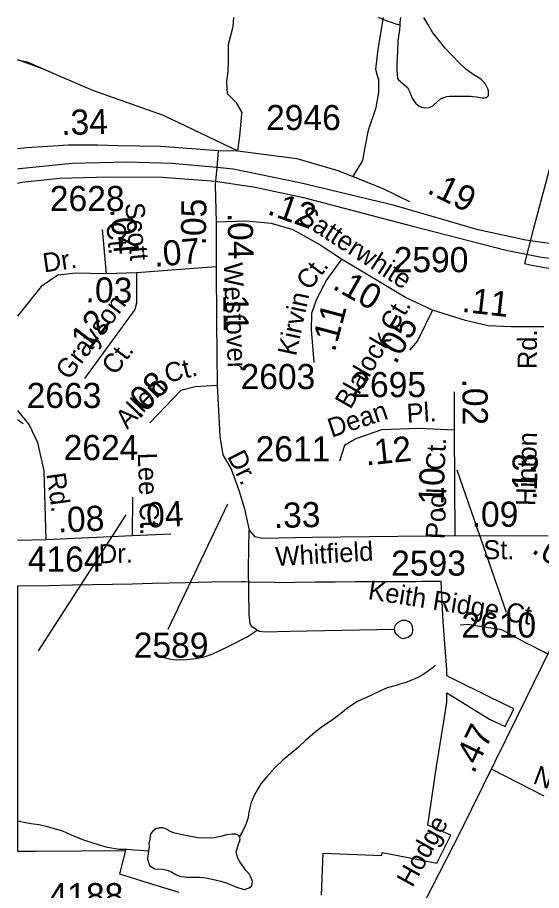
# Model space of a CAD drawing. Extents: x 2169602 to 2449496, y 721995 to 810662.
# Drawn here: x 2379098 to 2381705, y 806315 to 810662 of the extents above; entities that cross this region are included whole.
import ezdxf

# ---------------------------------------------------------------- set-up
doc = ezdxf.new("R2010")
doc.units = 0
doc.layers.add('Default', color=7, linetype='Continuous')

msp = doc.modelspace()

# ---------------------------------------------------------------- linework, layer by layer
at = {"layer": 'Default'}
for p, q in [((2379126, 808638.6), (2379098.1, 808658.4)), ((2381284, 808409.5), (2381529.1, 807700.8)), ((2379670.9, 808080.7), (2379671.6, 808273.1)), ((2380143.7, 808238.9), (2379845.3, 807615.5)), ((2379637.5, 808185.7), (2379200.6, 807509)), ((2379098.1, 807830.9), (2379098.1, 806511.6)), ((2379098.1, 807830.9), (2379098.1, 806511.6)), ((2381454.4, 806921), (2381716.7, 806787.4))]:
    msp.add_line(p, q, dxfattribs=at)
for points in [[(2380143.7, 810371.9), (2380144.2, 810376.4), (2380148.1, 810425.5), (2380148.1, 810527.6), (2380171.5, 810617.4), (2380173.9, 810661.8)], [(2380889.3, 810371.9), (2380880.1, 810401.9), (2380891.9, 810504), (2380919.1, 810661.8)], [(2381000.4, 810623), (2380986.2, 810627.2), (2380954.1, 810638.9), (2380928.2, 810646.9), (2380894.5, 810661.8)], [(2381000.4, 810623), (2380998.3, 810601), (2380990.4, 810545), (2380988.7, 810491.3), (2380984.8, 810433), (2380985.2, 810397.3), (2380989.1, 810359), (2380993.6, 810351), (2381027.3, 810323.2), (2381037.7, 810313.5), (2381049.8, 810289.4), (2381055.8, 810271.4), (2381063.6, 810257.7), (2381067.9, 810249.7), (2381080, 810233.7), (2381096, 810219.5), (2381108.1, 810215.6), (2381127.7, 810211.8), (2381146, 810213.9), (2381163.8, 810221.8), (2381188, 810244.1), (2381202, 810256.2), (2381213.9, 810262.1), (2381233.7, 810268.4), (2381247.7, 810270.4), (2381255.7, 810270.4), (2381279.5, 810270.4), (2381311.9, 810270.4), (2381329.7, 810270.5), (2381353.5, 810270.6), (2381363.8, 810268.6), (2381381.8, 810266.7), (2381409.7, 810260.9), (2381421.6, 810261.1), (2381429.6, 810263.2), (2381437.8, 810269.2), (2381441.5, 810273.1), (2381441.5, 810281.2), (2381441.7, 810297), (2381437.8, 810306.9), (2381425.7, 810329), (2381413.4, 810345.1), (2381403.1, 810354.8), (2381373, 810372.7), (2381351, 810388.6), (2381329.1, 810404.5), (2381290.8, 810440.3), (2381268.8, 810464.3), (2381247.1, 810486.3), (2381232.7, 810502.2), (2381224.7, 810510.3), (2381182.5, 810563.8), (2381164.2, 810586), (2381140, 810627.8), (2381119.9, 810661.7), (2381119.9, 810661.8)], [(2381002.9, 810661.8), (2381000.2, 810637.2), (2381000.4, 810623)], [(2379098.1, 810452.7), (2379220.3, 810407)], [(2379098.1, 810451.3), (2379145.8, 810440.2), (2379305, 810371.9)], [(2379305, 810371.9), (2379472, 810300.3), (2379823.1, 810175.8), (2380194.7, 809998.5)], [(2380214.7, 810182), (2380215.4, 810188.9), (2380187.9, 810236), (2380142.3, 810282.2), (2380140.3, 810343), (2380143.7, 810371.9)], [(2380828.2, 810016.2), (2380844.8, 810101.5), (2380882.1, 810213.5), (2380895.8, 810288.1), (2380895.8, 810350.9), (2380889.3, 810371.9)], [(2380194.7, 809998.5), (2380203.6, 810071.1), (2380214.7, 810182)], [(2381786.2, 810064.4), (2381661.9, 809599.8), (2381620.9, 809437.3), (2381648.9, 809431), (2381685.2, 809424), (2381873.7, 809388.8)], [(2381786.2, 810064.4), (2381661.9, 809599.8), (2381620.9, 809437.3), (2381648.9, 809431), (2381685.2, 809424), (2381873.7, 809388.8)], [(2379098.1, 810008.9), (2379143.1, 810014.4), (2379351.5, 810027.6), (2379497, 810027.6), (2379599.6, 810024.3), (2379811.3, 810021), (2380096.9, 810000.3)], [(2380096.9, 810000.3), (2380089.6, 809914.7)], [(2380096.9, 810000.3), (2380194.7, 809998.5), (2380487.1, 809959.2), (2380691.2, 809900.3), (2380913, 809812), (2381048.8, 809746)], [(2380767.6, 809870.7), (2380815.4, 809950.4), (2380828.2, 810016.2)], [(2380089.6, 809914.7), (2379865.3, 809935.5), (2379644.5, 809940.7), (2379369.8, 809934.5), (2379106.1, 809908.3), (2379098.1, 809906.9)], [(2380089.6, 809914.7), (2380083.8, 809846.1)], [(2382949.4, 809552.5), (2382701, 809534.5), (2382315.9, 809508.3), (2382194.7, 809502.1), (2382060.6, 809508.3), (2381834.6, 809522.9), (2381626.8, 809553.3), (2381390.4, 809604.6), (2380973.9, 809726.1), (2380503, 809839.2), (2380170.8, 809906.2), (2380089.6, 809914.7)], [(2379098.1, 809837.6), (2379120, 809841.3), (2379307.3, 809862.2), (2379553.2, 809868.5), (2379819.5, 809867.4), (2380083.8, 809846.1)], [(2380083.8, 809846.1), (2380082.1, 809826.5), (2380086.3, 809643.2)], [(2380083.8, 809846.1), (2380280.1, 809817.2), (2380521.3, 809764.8), (2381052.4, 809626.6), (2381529.5, 809504.1), (2381704.8, 809468.5), (2381953.8, 809440.2), (2382139.7, 809431.2), (2382237.6, 809433.1), (2382474.4, 809448), (2382739.6, 809467.6), (2382948.5, 809482.5)], [(2380709.4, 809458.9), (2380593.3, 809534.3), (2380468.8, 809604.5), (2380361, 809635.9), (2380234.4, 809648.5), (2380086.3, 809643.2)], [(2380086.3, 809643.2), (2380086.3, 809420.2)], [(2379541.7, 809385.6), (2379520.7, 809605.5)], [(2380709.4, 809458.9), (2380637.8, 809357.4), (2380585.4, 809258.9), (2380561.4, 809187.7), (2380559.3, 809108.2), (2380572.4, 808943.8)], [(2381163.1, 809204.5), (2381028.1, 809268.4), (2380709.4, 809458.9)], [(2380086.3, 809420.2), (2379690.3, 809389.8)], [(2380086.3, 809420.2), (2380088.9, 809148), (2380092.1, 808829.6)], [(2379541.7, 809385.6), (2379386.3, 809388.8), (2379299.4, 809379.4), (2379216.8, 809322.8), (2379098.1, 809174.2)], [(2379690.3, 809389.8), (2379690.8, 809240.1), (2379681.4, 809207.6), (2379431.8, 808865.2)], [(2379690.3, 809389.8), (2379541.7, 809385.6)], [(2381163.1, 809204.5), (2381088.8, 809052.7), (2381047.9, 809005.5)], [(2381716.1, 809121.8), (2381553.9, 809121.8), (2381438.8, 809127), (2381326.8, 809153.2), (2381163.1, 809204.5)], [(2380092.1, 808829.6), (2379981.3, 808823), (2379910.4, 808805.2), (2379756.4, 808643.4)], [(2380092.1, 808829.6), (2380104.6, 808577.3), (2380119.3, 808485.1), (2380161.1, 808413.9), (2380198.8, 808309.2), (2380228.1, 808215), (2380251.1, 808110.2), (2380278.3, 808075.7)], [(2381271.9, 808607.6), (2381272.4, 808798.2)], [(2379098.1, 808704.7), (2379156.1, 808633.8), (2379197.9, 808545.9), (2379228.8, 808405.5), (2379238.7, 808061)], [(2381271.9, 808607.6), (2381092.4, 808615), (2380909.3, 808608.7), (2380781.6, 808563.7), (2380725.1, 808530.1), (2380700, 808452.7)], [(2381275, 808080.9), (2381271.9, 808607.6)], [(2379860.3, 808089.3), (2379670.9, 808080.7)], [(2380290.6, 807611.1), (2380267.5, 807626.5), (2380255.9, 807642.4), (2380250.9, 807690.3), (2380247.7, 807920.1), (2380251.1, 808110.2)], [(2379238.7, 808061), (2379098.1, 808058.7)], [(2379670.9, 808080.7), (2379238.7, 808061)], [(2381275, 808080.9), (2380563.5, 808072.6), (2380315, 808068.4), (2380278.3, 808075.7)], [(2381738.6, 808078.8), (2381275, 808080.9)], [(2381988.7, 807976.2), (2381868.8, 807764.7), (2381583.2, 807182.5), (2381299.6, 806606.6), (2381090.3, 806194), (2380977.8, 805995)], [(2380610.2, 806292.6), (2380619.2, 806502.2), (2380910.7, 806489.5), (2380911.7, 806505.3), (2380989.7, 806490), (2381184.9, 806451.9), (2381227.9, 806537.4), (2381254.7, 806591.3), (2381139.9, 806641.6), (2381182.9, 806932.5), (2381218.9, 807156.4), (2381234.7, 807252.9), (2381234.4, 807299.1), (2381445.7, 807167.9), (2381523.4, 807132.6), (2381566.9, 807220.4), (2381438.4, 807283.6), (2381274.4, 807364.3), (2381233.9, 807384.3), (2381233.7, 807415.4), (2381216.2, 807652.7), (2381205.7, 807854.3), (2381177.9, 807853.9), (2381110.7, 807853.3), (2381077.9, 807853), (2380997.9, 807852.4), (2380976.9, 807852.4), (2380879.2, 807852.4), (2380779.7, 807851.7), (2380679.2, 807850.7), (2380578.7, 807849.8), (2380479.7, 807848.7), (2380397.2, 807847.8), (2380379.4, 807849.4), (2380374.4, 807849.9), (2380277.4, 807849.4), (2380226.9, 807853), (2380211.9, 807852.3), (2380063.2, 807850.1), (2379933.9, 807847.7), (2379770.4, 807844.1), (2379669.9, 807840.7), (2379570.2, 807839.1), (2379471.4, 807837.1), (2379371.2, 807836.1), (2379254.4, 807833.1), (2379098.1, 807830.9)], [(2380610.2, 806292.6), (2380619.2, 806502.2), (2380910.7, 806489.5), (2380911.7, 806505.3), (2380989.7, 806490), (2381184.9, 806451.9), (2381227.9, 806537.4), (2381254.7, 806591.3), (2381139.9, 806641.6), (2381182.9, 806932.5), (2381218.9, 807156.4), (2381234.7, 807252.9), (2381234.4, 807299.1), (2381445.7, 807167.9), (2381523.4, 807132.6), (2381566.9, 807220.4), (2381438.4, 807283.6), (2381274.4, 807364.3), (2381233.9, 807384.3), (2381233.7, 807415.4), (2381216.2, 807652.7), (2381205.7, 807854.3), (2381177.9, 807853.9), (2381110.7, 807853.3), (2381077.9, 807853), (2380997.9, 807852.4), (2380976.9, 807852.4), (2380879.2, 807852.4), (2380779.7, 807851.7), (2380679.2, 807850.7), (2380578.7, 807849.8), (2380479.7, 807848.7), (2380397.2, 807847.8), (2380379.4, 807849.4), (2380374.4, 807849.9), (2380277.4, 807849.4), (2380226.9, 807853), (2380211.9, 807852.3), (2380063.2, 807850.1), (2379933.9, 807847.7), (2379770.4, 807844.1), (2379669.9, 807840.7), (2379570.2, 807839.1), (2379471.4, 807837.1), (2379371.2, 807836.1), (2379254.4, 807833.1), (2379098.1, 807830.9)], [(2380973, 807615.9), (2380974.7, 807629.9), (2380980.4, 807640), (2380990.4, 807649.8), (2381000.1, 807656.6), (2381012, 807660.7), (2381022.6, 807661.1), (2381030.6, 807660.9), (2381046, 807655.4), (2381054.2, 807646.5), (2381058.5, 807639.8), (2381061.9, 807630.3), (2381063.6, 807618.3), (2381063.2, 807607.9), (2381059.5, 807593.7), (2381053, 807584.5), (2381041.8, 807575.3), (2381034.8, 807572.9), (2381027.9, 807571), (2381016.7, 807569.2), (2381010, 807570.8), (2380997.7, 807576.4), (2380989.7, 807584.2), (2380985.6, 807588.1), (2380977.2, 807600), (2380973, 807615.9)], [(2379793, 807484.2), (2379809.5, 807479.9), (2379853.2, 807469), (2379887, 807464.3), (2379938.9, 807465.3), (2379983, 807470.4), (2380027, 807479.5), (2380067.2, 807492.6), (2380145.8, 807531), (2380240.6, 807579.1), (2380290.6, 807611.1)], [(2380290.6, 807611.1), (2380300.7, 807607.3), (2380332.7, 807604), (2380452.7, 807606.6), (2380973, 807615.9)], [(2381300.4, 807638.9), (2381340.2, 807641.1), (2381366.8, 807636.7), (2381506.4, 807614.5), (2381615, 807554.7), (2381736.1, 807494.1)], [(2381178.2, 807436.9), (2381160.5, 807422.6), (2381142.5, 807408.6), (2381114.4, 807388.5), (2381086.5, 807374.5), (2381054.5, 807360.3), (2381026.4, 807349.9), (2381000.4, 807342.1), (2380982.4, 807335.9), (2380937, 807323.7), (2380900.7, 807307.7), (2380858.7, 807287.3), (2380787.1, 807255.1), (2380735.5, 807220.7), (2380697.3, 807188.8), (2380653.2, 807156.5), (2380615.3, 807132.3), (2380609.6, 807126.2), (2380578, 807102.2), (2380532.1, 807064.1), (2380495.8, 807029.8), (2380464.4, 807001.8), (2380420.5, 806965.4), (2380378.5, 806925.5), (2380338.9, 806881.2), (2380309, 806847.2), (2380297.1, 806827), (2380277.6, 806791.1), (2380261, 806753), (2380253.6, 806727), (2380249.5, 806704.9), (2380245.6, 806678.7), (2380239.9, 806658.9), (2380235.6, 806649), (2380229.8, 806634.8), (2380218.3, 806608.6), (2380207.9, 806592.7), (2380201.9, 806584.7)], [(2379750.6, 806510.6), (2379744.7, 806510.7), (2379706.5, 806514.4), (2379676.8, 806516.5), (2379642.5, 806520.4), (2379604.6, 806520.1), (2379546.4, 806529.7), (2379480.3, 806549.5), (2379428.7, 806565.4), (2379366.1, 806591.1), (2379324.5, 806610.8), (2379294.4, 806618.6), (2379248.2, 806632.5), (2379206.4, 806642.4), (2379164.4, 806648), (2379114.3, 806658), (2379101.8, 806659.9), (2379098.1, 806661.9)], [(2380201.9, 806584.7), (2380200.1, 806588.6), (2380183.9, 806596.8), (2380166, 806596.6), (2380137.7, 806592.4), (2380110.1, 806584.4), (2380078.5, 806578.2), (2380036.4, 806576.1), (2379994.2, 806578), (2379944.4, 806587.5), (2379926.3, 806591.5), (2379874.5, 806603.4), (2379854, 806611), (2379840, 806621.2), (2379821.8, 806627.2), (2379809.9, 806627), (2379802.3, 806626.9), (2379786.3, 806622.9), (2379772.3, 806610.8), (2379762.3, 806598.9), (2379758.2, 806586.9), (2379756.3, 806570.6), (2379752.2, 806548.9), (2379752.7, 806532.6), (2379750.6, 806510.6)], [(2379750.6, 806510.6), (2379746.7, 806486.9), (2379744.7, 806472.6), (2379746.7, 806464.6), (2379750.8, 806450.9), (2379752.9, 806445), (2379757, 806438.7), (2379781, 806422.8), (2379818.9, 806421.1), (2379842.9, 806417.1), (2379865, 806409.3), (2379885.3, 806395.3), (2379905.2, 806387.4), (2379939, 806381.5), (2379964.9, 806381.6), (2380005.1, 806382.1), (2380035, 806377.9), (2380080.9, 806368.1), (2380109.2, 806362.2), (2380141.2, 806352.6), (2380173.2, 806338.8), (2380193.3, 806330.9), (2380211.4, 806324.9), (2380225.1, 806320.8), (2380231, 806321.1), (2380241.1, 806324.8), (2380251.1, 806329), (2380263, 806336.9), (2380265.3, 806347.2), (2380267.1, 806361.1), (2380261.2, 806379), (2380251.3, 806398.7), (2380234.9, 806415), (2380226.5, 806428.8), (2380204.8, 806458.9), (2380194.5, 806476.7), (2380188.8, 806492.6), (2380186.8, 806508.7), (2380194.5, 806534.7), (2380200.1, 806550.9), (2380206, 806568.7), (2380204.4, 806578.7), (2380201.9, 806584.7)], [(2379098.1, 806511.6), (2379191.7, 806510.9), (2379636.2, 806514.2), (2379605.7, 806398.1), (2379748.7, 806353.9), (2379900.9, 806306.8)], [(2379098.1, 806511.6), (2379191.7, 806510.9), (2379636.2, 806514.2), (2379605.7, 806398.1), (2379748.7, 806353.9), (2379900.9, 806306.8)]]:
    msp.add_lwpolyline(points, dxfattribs=at)

# ---------------------------------------------------------------- texts
for s, height, p in [('2946', 125, (2380334.7, 810101)), ('2628', 125, (2379259.1, 809697.9)), ('2590', 125, (2380969.5, 809393.6)), ('2603', 125, (2380207.7, 808811.5)), ('2695', 125, (2380758.8, 808771.7)), ('2663', 125, (2379143.7, 808717.7)), ('2624', 125, (2379327.8, 808458.5)), ('2611', 125, (2380282.6, 808451.9)), ('.09', 125, (2381357.5, 808126.3)), ('St.', 95, (2381415.2, 807964.7)), ('4164', 125, (2379149.3, 807903.2)), ('2593', 125, (2380956.8, 807882.9)), ('2610', 125, (2381306.3, 807574.7)), ('2589', 125, (2379676.6, 807474.5)), ('4188', 125, (2379252.7, 806227.3))]:
    msp.add_text(s, height=height, dxfattribs=at).set_placement(p)
for s, height, rotation, p in [('.34', 125, 1.3105, (2379317, 810076.3)), ('.19', 125, 334.0793, (2381129.8, 809790)), ('.05', 125, 89.104, (2380035.4, 809526.2)), ('.12', 125, 340.7006, (2380335.9, 809683.9)), ('Scott', 95, 275.069, (2379633.5, 809736)), ('Satterwhite', 95, 326.9627, (2380486.8, 809651.8)), ('.04', 125, 275.069, (2379558.6, 809709)), ('.04', 125, 271.1866, (2380143.2, 809688.5)), ('Ct.', 95, 275.069, (2379539.5, 809640.5)), ('.07', 125, 5.0543, (2379780.3, 809420.1)), ('Dr.', 95, 8.1339, (2379230.6, 809392.3)), ('Westover', 95, 272.2565, (2380123.8, 809440.2)), ('Ct.', 95, 52.1394, (2380551.2, 809298.1)), ('.03', 125, 359.0285, (2379436.1, 809244.3)), ('.10', 125, 330.5304, (2380659.6, 809314.1)), ('.11', 125, 270.2899, (2380122.2, 809329.5)), ('.11', 125, 353.4503, (2381305.1, 809196.6)), ('Grayson', 95, 53.144, (2379355.9, 808852.1)), ('Kirvin', 95, 77.9115, (2380483.9, 808972.5)), ('Blalock Ct.', 95, 59.8622, (2380754.4, 808706.6)), ('.12', 125, 53.144, (2379425.1, 808960.9)), ('.11', 125, 75.0759, (2380676.8, 808992.5)), ('.05', 125, 59.8622, (2380979.2, 808930.6)), ('Rd.', 95, 89.6362, (2381681.2, 808910.7)), ('Ct.', 95, 53.144, (2379584.7, 808875.8)), ('Ct.', 95, 14.0433, (2379842.4, 808841.5)), ('.08', 125, 46.4273, (2379702.7, 808657.9)), ('Allen', 95, 46.4273, (2379644.3, 808607.9)), ('.02', 125, 270.5206, (2381311.2, 808863.8)), ('Pl.', 95, 3.2535, (2381036.7, 808643.3)), ('Dean', 95, 18.4441, (2380660.3, 808569.6)), ('.12', 125, 6.0118, (2380832.5, 808430.7)), ('Hinton', 95, 88.4294, (2381673.1, 808229.1)), ('Ct.', 95, 87.9561, (2381224.2, 808405.3)), ('Lee Ct.', 95, 271.9296, (2379696.4, 808493.4)), ('Dr.', 95, 296.5532, (2380139.8, 808477.2)), ('.13', 125, 88.4294, (2381680.7, 808258.9)), ('Rd.', 95, 277.8974, (2379242.1, 808389.6)), ('.10', 125, 87.9561, (2381215.8, 808188.3)), ('Pool', 95, 87.9561, (2381223.4, 808063.4)), ('.08', 125, 2.6135, (2379300.8, 808097.2)), ('.04', 125, 2.6046, (2379694.5, 808119.8)), ('.33', 125, 1.2474, (2380374, 808120.2)), ('Whitfield', 95, 3.304, (2380384.2, 807930.3)), ('.05', 125, 327.2513, (2381650.6, 808001.3)), ('Dr.', 95, 1.1819, (2379503.7, 807944.1)), ('Keith Ridge Ct.', 95, 350.9758, (2380838.3, 807766.6)), ('.47', 125, 64.1448, (2381368, 806893.2)), ('Needwill Ct.', 95, 339.2897, (2381657.2, 806851.1)), ('Hodge', 95, 61.0118, (2381062.5, 806326.6))]:
    msp.add_text(s, height=height, rotation=rotation, dxfattribs=at).set_placement(p)

doc.saveas('drawing.dxf')
